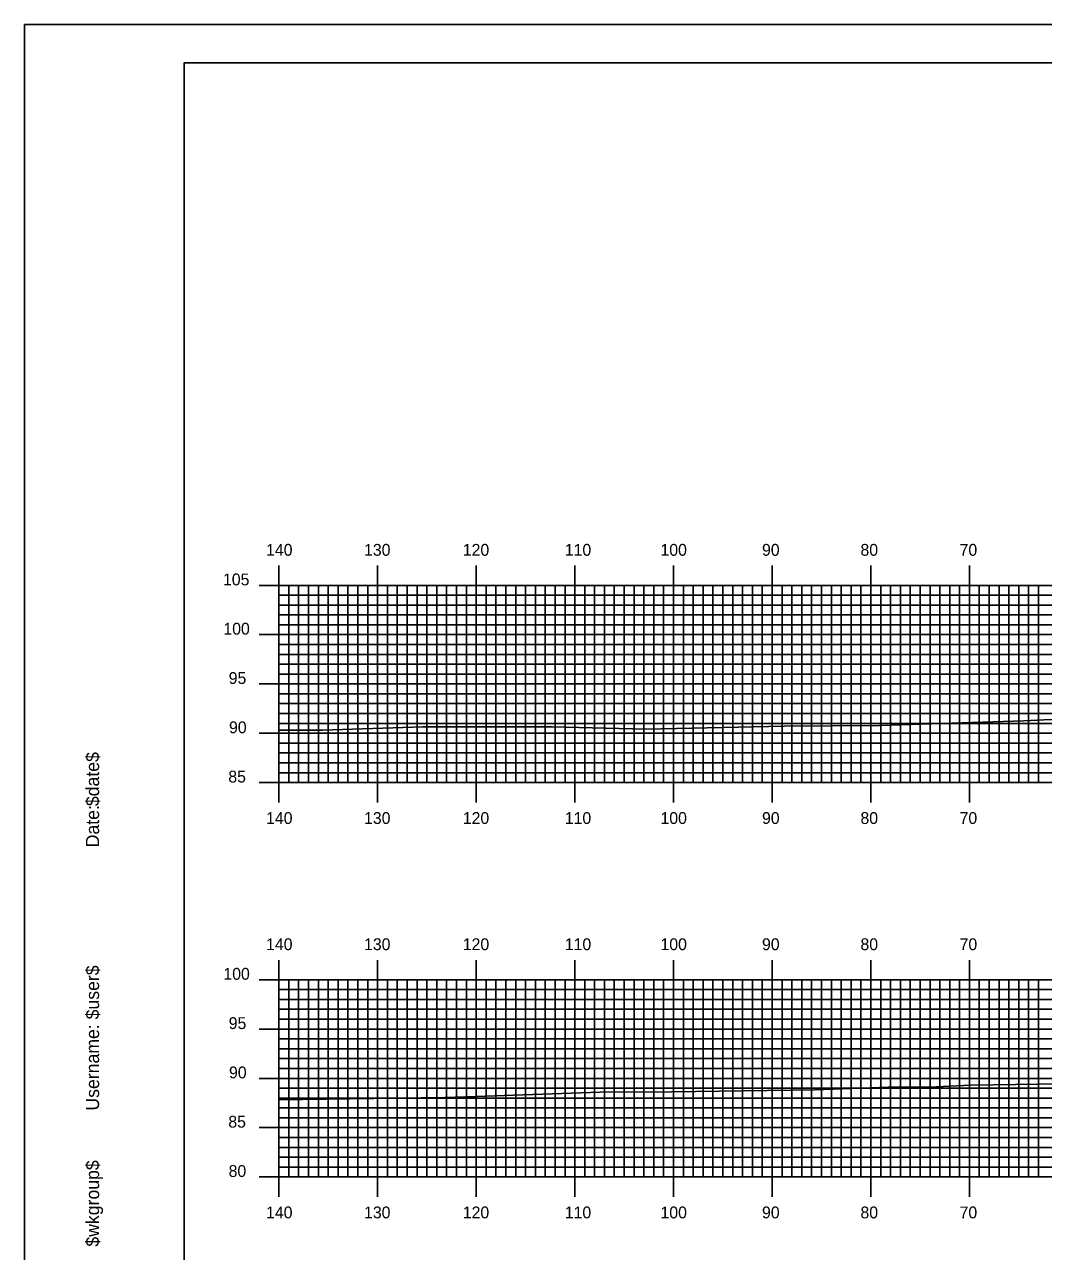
# Model space of a CAD drawing. Extents: x 1777925 to 1778268, y 442591 to 442811.
# Drawn here: x 1777925 to 1778028.3, y 442686.1 to 442810.5 of the extents above; entities that cross this region are included whole.
import ezdxf

# ---------------------------------------------------------------- set-up
doc = ezdxf.new("R2010")
doc.units = 0
for name, color, linetype in [('BORDER', 7, 'Continuous'), ('H_V ANNOTATION', 7, 'Continuous'), ('MAJOR', 7, 'Continuous'), ('MINOR', 7, 'Continuous'), ('PLOT BOUNDARY', 7, 'Continuous'), ('S_Roadway_Centerline', 7, 'Continuous')]:
    doc.layers.add(name, color=color, linetype=linetype)

msp = doc.modelspace()

# ---------------------------------------------------------------- linework, layer by layer
at = {"layer": 'BORDER'}
msp.add_lwpolyline([(1777941.19, 442596.67), (1778261.19, 442596.67), (1778261.19, 442806.67), (1777941.19, 442806.67)], close=True, dxfattribs=at)
at = {"layer": 'MAJOR'}
for p, q in [((1777950.79, 442755.67), (1777950.79, 442753.67)), ((1777960.79, 442755.67), (1777960.79, 442753.67)), ((1777970.79, 442755.67), (1777970.79, 442753.67)), ((1777980.79, 442755.67), (1777980.79, 442753.67)), ((1777990.79, 442755.67), (1777990.79, 442753.67)), ((1778000.79, 442755.67), (1778000.79, 442753.67)), ((1778010.79, 442755.67), (1778010.79, 442753.67)), ((1778020.79, 442755.67), (1778020.79, 442753.67)), ((1777948.79, 442753.67), (1777950.79, 442753.67)), ((1777950.79, 442753.67), (1778230.79, 442753.67)), ((1777950.79, 442733.67), (1777950.79, 442753.67)), ((1777950.79, 442733.67), (1777950.79, 442753.67)), ((1777950.79, 442753.67), (1778230.79, 442753.67)), ((1777960.79, 442733.67), (1777960.79, 442753.67)), ((1777970.79, 442733.67), (1777970.79, 442753.67)), ((1777980.79, 442733.67), (1777980.79, 442753.67)), ((1777990.79, 442733.67), (1777990.79, 442753.67)), ((1778000.79, 442733.67), (1778000.79, 442753.67)), ((1778010.79, 442733.67), (1778010.79, 442753.67)), ((1778020.79, 442733.67), (1778020.79, 442753.67)), ((1777948.79, 442748.67), (1777950.79, 442748.67)), ((1777950.79, 442748.67), (1778230.79, 442748.67)), ((1777948.79, 442743.67), (1777950.79, 442743.67)), ((1777950.79, 442743.67), (1778230.79, 442743.67)), ((1777948.79, 442738.67), (1777950.79, 442738.67)), ((1777950.79, 442738.67), (1778230.79, 442738.67)), ((1777948.79, 442733.67), (1777950.79, 442733.67)), ((1777950.79, 442733.67), (1778230.79, 442733.67)), ((1777950.79, 442733.67), (1778230.79, 442733.67)), ((1777950.79, 442731.66), (1777950.79, 442733.67)), ((1777960.79, 442731.66), (1777960.79, 442733.67)), ((1777970.79, 442731.66), (1777970.79, 442733.67)), ((1777980.79, 442731.66), (1777980.79, 442733.67)), ((1777990.79, 442731.66), (1777990.79, 442733.67)), ((1778000.79, 442731.66), (1778000.79, 442733.67)), ((1778010.79, 442731.66), (1778010.79, 442733.67)), ((1778020.79, 442731.66), (1778020.79, 442733.67)), ((1777950.79, 442715.67), (1777950.79, 442713.67)), ((1777960.79, 442715.67), (1777960.79, 442713.67)), ((1777970.79, 442715.67), (1777970.79, 442713.67)), ((1777980.79, 442715.67), (1777980.79, 442713.67)), ((1777990.79, 442715.67), (1777990.79, 442713.67)), ((1778000.79, 442715.67), (1778000.79, 442713.67)), ((1778010.79, 442715.67), (1778010.79, 442713.67)), ((1778020.79, 442715.67), (1778020.79, 442713.67)), ((1777948.79, 442713.67), (1777950.79, 442713.67)), ((1777950.79, 442713.67), (1778230.79, 442713.67)), ((1777950.79, 442693.67), (1777950.79, 442713.67)), ((1777950.79, 442693.67), (1777950.79, 442713.67)), ((1777950.79, 442713.67), (1778230.79, 442713.67)), ((1777960.79, 442693.67), (1777960.79, 442713.67)), ((1777970.79, 442693.67), (1777970.79, 442713.67)), ((1777980.79, 442693.67), (1777980.79, 442713.67)), ((1777990.79, 442693.67), (1777990.79, 442713.67)), ((1778000.79, 442693.67), (1778000.79, 442713.67)), ((1778010.79, 442693.67), (1778010.79, 442713.67)), ((1778020.79, 442693.67), (1778020.79, 442713.67)), ((1777948.79, 442708.67), (1777950.79, 442708.67)), ((1777950.79, 442708.67), (1778230.79, 442708.67)), ((1777948.79, 442703.67), (1777950.79, 442703.67)), ((1777950.79, 442703.67), (1778230.79, 442703.67)), ((1777948.79, 442698.67), (1777950.79, 442698.67)), ((1777950.79, 442698.67), (1778230.79, 442698.67)), ((1777948.79, 442693.67), (1777950.79, 442693.67)), ((1777950.79, 442693.67), (1778230.79, 442693.67)), ((1777950.79, 442693.67), (1778230.79, 442693.67)), ((1777950.79, 442691.66), (1777950.79, 442693.67)), ((1777960.79, 442691.66), (1777960.79, 442693.67)), ((1777970.79, 442691.66), (1777970.79, 442693.67)), ((1777980.79, 442691.66), (1777980.79, 442693.67)), ((1777990.79, 442691.66), (1777990.79, 442693.67)), ((1778000.79, 442691.66), (1778000.79, 442693.67)), ((1778010.79, 442691.66), (1778010.79, 442693.67)), ((1778020.79, 442691.66), (1778020.79, 442693.67))]:
    msp.add_line(p, q, dxfattribs=at)
at = {"layer": 'MINOR'}
for p, q in [((1777950.79, 442752.67), (1778230.79, 442752.67)), ((1777950.79, 442752.67), (1777952.79, 442752.67)), ((1777951.79, 442733.67), (1777951.79, 442753.67)), ((1777952.79, 442733.67), (1777952.79, 442753.67)), ((1777953.79, 442733.67), (1777953.79, 442753.67)), ((1777954.79, 442733.67), (1777954.79, 442753.67)), ((1777955.79, 442733.67), (1777955.79, 442753.67)), ((1777956.79, 442733.67), (1777956.79, 442753.67)), ((1777957.79, 442733.67), (1777957.79, 442753.67)), ((1777958.79, 442733.67), (1777958.79, 442753.67)), ((1777959.79, 442733.67), (1777959.79, 442753.67)), ((1777961.79, 442733.67), (1777961.79, 442753.67)), ((1777962.79, 442733.67), (1777962.79, 442753.67)), ((1777963.79, 442733.67), (1777963.79, 442753.67)), ((1777964.79, 442733.67), (1777964.79, 442753.67)), ((1777965.79, 442733.67), (1777965.79, 442753.67)), ((1777966.79, 442733.67), (1777966.79, 442753.67)), ((1777967.79, 442733.67), (1777967.79, 442753.67)), ((1777968.79, 442733.67), (1777968.79, 442753.67)), ((1777969.79, 442733.67), (1777969.79, 442753.67)), ((1777971.79, 442733.67), (1777971.79, 442753.67)), ((1777972.79, 442733.67), (1777972.79, 442753.67)), ((1777973.79, 442733.67), (1777973.79, 442753.67)), ((1777974.79, 442733.67), (1777974.79, 442753.67)), ((1777975.79, 442733.67), (1777975.79, 442753.67)), ((1777976.79, 442733.67), (1777976.79, 442753.67)), ((1777977.79, 442733.67), (1777977.79, 442753.67)), ((1777978.79, 442733.67), (1777978.79, 442753.67)), ((1777979.79, 442733.67), (1777979.79, 442753.67)), ((1777981.79, 442733.67), (1777981.79, 442753.67)), ((1777982.79, 442733.67), (1777982.79, 442753.67)), ((1777983.79, 442733.67), (1777983.79, 442753.67)), ((1777984.79, 442733.67), (1777984.79, 442753.67)), ((1777985.79, 442733.67), (1777985.79, 442753.67)), ((1777986.79, 442733.67), (1777986.79, 442753.67)), ((1777987.79, 442733.67), (1777987.79, 442753.67)), ((1777988.79, 442733.67), (1777988.79, 442753.67)), ((1777989.79, 442733.67), (1777989.79, 442753.67)), ((1777991.79, 442733.67), (1777991.79, 442753.67)), ((1777992.79, 442733.67), (1777992.79, 442753.67)), ((1777993.79, 442733.67), (1777993.79, 442753.67)), ((1777994.79, 442733.67), (1777994.79, 442753.67)), ((1777995.79, 442733.67), (1777995.79, 442753.67)), ((1777996.79, 442733.67), (1777996.79, 442753.67)), ((1777997.79, 442733.67), (1777997.79, 442753.67)), ((1777998.79, 442733.67), (1777998.79, 442753.67)), ((1777999.79, 442733.67), (1777999.79, 442753.67)), ((1778001.79, 442733.67), (1778001.79, 442753.67)), ((1778002.79, 442733.67), (1778002.79, 442753.67)), ((1778003.79, 442733.67), (1778003.79, 442753.67)), ((1778004.79, 442733.67), (1778004.79, 442753.67)), ((1778005.79, 442733.67), (1778005.79, 442753.67)), ((1778006.79, 442733.67), (1778006.79, 442753.67)), ((1778007.79, 442733.67), (1778007.79, 442753.67)), ((1778008.79, 442733.67), (1778008.79, 442753.67)), ((1778009.79, 442733.67), (1778009.79, 442753.67)), ((1778011.79, 442733.67), (1778011.79, 442753.67)), ((1778012.79, 442733.67), (1778012.79, 442753.67)), ((1778013.79, 442733.67), (1778013.79, 442753.67)), ((1778014.79, 442733.67), (1778014.79, 442753.67)), ((1778015.79, 442733.67), (1778015.79, 442753.67)), ((1778016.79, 442733.67), (1778016.79, 442753.67)), ((1778017.79, 442733.67), (1778017.79, 442753.67)), ((1778018.79, 442733.67), (1778018.79, 442753.67)), ((1778019.79, 442733.67), (1778019.79, 442753.67)), ((1778021.79, 442733.67), (1778021.79, 442753.67)), ((1778022.79, 442733.67), (1778022.79, 442753.67)), ((1778023.79, 442733.67), (1778023.79, 442753.67)), ((1778024.79, 442733.67), (1778024.79, 442753.67)), ((1778025.79, 442733.67), (1778025.79, 442753.67)), ((1778026.79, 442733.67), (1778026.79, 442753.67)), ((1778027.79, 442733.67), (1778027.79, 442753.67)), ((1777950.79, 442751.67), (1778230.79, 442751.67)), ((1777950.79, 442751.67), (1777952.79, 442751.67)), ((1777950.79, 442750.67), (1778230.79, 442750.67)), ((1777950.79, 442750.67), (1777952.79, 442750.67)), ((1777950.79, 442749.67), (1778230.79, 442749.67)), ((1777950.79, 442749.67), (1777952.79, 442749.67)), ((1777950.79, 442747.67), (1778230.79, 442747.67)), ((1777950.79, 442747.67), (1777952.79, 442747.67)), ((1777950.79, 442746.67), (1778230.79, 442746.67)), ((1777950.79, 442746.67), (1777952.79, 442746.67)), ((1777950.79, 442745.67), (1778230.79, 442745.67)), ((1777950.79, 442745.67), (1777952.79, 442745.67)), ((1777950.79, 442744.67), (1778230.79, 442744.67)), ((1777950.79, 442744.67), (1777952.79, 442744.67)), ((1777950.79, 442742.67), (1778230.79, 442742.67)), ((1777950.79, 442742.67), (1777952.79, 442742.67)), ((1777950.79, 442741.67), (1778230.79, 442741.67)), ((1777950.79, 442741.67), (1777952.79, 442741.67)), ((1777950.79, 442740.67), (1778230.79, 442740.67)), ((1777950.79, 442740.67), (1777952.79, 442740.67)), ((1777950.79, 442739.67), (1778230.79, 442739.67)), ((1777950.79, 442739.67), (1777952.79, 442739.67)), ((1777950.79, 442737.67), (1778230.79, 442737.67)), ((1777950.79, 442737.67), (1777952.79, 442737.67)), ((1777950.79, 442736.67), (1778230.79, 442736.67)), ((1777950.79, 442736.67), (1777952.79, 442736.67)), ((1777950.79, 442735.67), (1778230.79, 442735.67)), ((1777950.79, 442735.67), (1777952.79, 442735.67)), ((1777950.79, 442734.67), (1778230.79, 442734.67)), ((1777950.79, 442734.67), (1777952.79, 442734.67)), ((1777951.79, 442693.67), (1777951.79, 442713.67)), ((1777952.79, 442693.67), (1777952.79, 442713.67)), ((1777953.79, 442693.67), (1777953.79, 442713.67)), ((1777954.79, 442693.67), (1777954.79, 442713.67)), ((1777955.79, 442693.67), (1777955.79, 442713.67)), ((1777956.79, 442693.67), (1777956.79, 442713.67)), ((1777957.79, 442693.67), (1777957.79, 442713.67)), ((1777958.79, 442693.67), (1777958.79, 442713.67)), ((1777959.79, 442693.67), (1777959.79, 442713.67)), ((1777961.79, 442693.67), (1777961.79, 442713.67)), ((1777962.79, 442693.67), (1777962.79, 442713.67)), ((1777963.79, 442693.67), (1777963.79, 442713.67)), ((1777964.79, 442693.67), (1777964.79, 442713.67)), ((1777965.79, 442693.67), (1777965.79, 442713.67)), ((1777966.79, 442693.67), (1777966.79, 442713.67)), ((1777967.79, 442693.67), (1777967.79, 442713.67)), ((1777968.79, 442693.67), (1777968.79, 442713.67)), ((1777969.79, 442693.67), (1777969.79, 442713.67)), ((1777971.79, 442693.67), (1777971.79, 442713.67)), ((1777972.79, 442693.67), (1777972.79, 442713.67)), ((1777973.79, 442693.67), (1777973.79, 442713.67)), ((1777974.79, 442693.67), (1777974.79, 442713.67)), ((1777975.79, 442693.67), (1777975.79, 442713.67)), ((1777976.79, 442693.67), (1777976.79, 442713.67)), ((1777977.79, 442693.67), (1777977.79, 442713.67)), ((1777978.79, 442693.67), (1777978.79, 442713.67)), ((1777979.79, 442693.67), (1777979.79, 442713.67)), ((1777981.79, 442693.67), (1777981.79, 442713.67)), ((1777982.79, 442693.67), (1777982.79, 442713.67)), ((1777983.79, 442693.67), (1777983.79, 442713.67)), ((1777984.79, 442693.67), (1777984.79, 442713.67)), ((1777985.79, 442693.67), (1777985.79, 442713.67)), ((1777986.79, 442693.67), (1777986.79, 442713.67)), ((1777987.79, 442693.67), (1777987.79, 442713.67)), ((1777988.79, 442693.67), (1777988.79, 442713.67)), ((1777989.79, 442693.67), (1777989.79, 442713.67)), ((1777991.79, 442693.67), (1777991.79, 442713.67)), ((1777992.79, 442693.67), (1777992.79, 442713.67)), ((1777993.79, 442693.67), (1777993.79, 442713.67)), ((1777994.79, 442693.67), (1777994.79, 442713.67)), ((1777995.79, 442693.67), (1777995.79, 442713.67)), ((1777996.79, 442693.67), (1777996.79, 442713.67)), ((1777997.79, 442693.67), (1777997.79, 442713.67)), ((1777998.79, 442693.67), (1777998.79, 442713.67)), ((1777999.79, 442693.67), (1777999.79, 442713.67)), ((1778001.79, 442693.67), (1778001.79, 442713.67)), ((1778002.79, 442693.67), (1778002.79, 442713.67)), ((1778003.79, 442693.67), (1778003.79, 442713.67)), ((1778004.79, 442693.67), (1778004.79, 442713.67)), ((1778005.79, 442693.67), (1778005.79, 442713.67)), ((1778006.79, 442693.67), (1778006.79, 442713.67)), ((1778007.79, 442693.67), (1778007.79, 442713.67)), ((1778008.79, 442693.67), (1778008.79, 442713.67)), ((1778009.79, 442693.67), (1778009.79, 442713.67)), ((1778011.79, 442693.67), (1778011.79, 442713.67)), ((1778012.79, 442693.67), (1778012.79, 442713.67)), ((1778013.79, 442693.67), (1778013.79, 442713.67)), ((1778014.79, 442693.67), (1778014.79, 442713.67)), ((1778015.79, 442693.67), (1778015.79, 442713.67)), ((1778016.79, 442693.67), (1778016.79, 442713.67)), ((1778017.79, 442693.67), (1778017.79, 442713.67)), ((1778018.79, 442693.67), (1778018.79, 442713.67)), ((1778019.79, 442693.67), (1778019.79, 442713.67)), ((1778021.79, 442693.67), (1778021.79, 442713.67)), ((1778022.79, 442693.67), (1778022.79, 442713.67)), ((1778023.79, 442693.67), (1778023.79, 442713.67)), ((1778024.79, 442693.67), (1778024.79, 442713.67)), ((1778025.79, 442693.67), (1778025.79, 442713.67)), ((1778026.79, 442693.67), (1778026.79, 442713.67)), ((1778027.79, 442693.67), (1778027.79, 442713.67)), ((1777950.79, 442712.67), (1778230.79, 442712.67)), ((1777950.79, 442712.67), (1777952.79, 442712.67)), ((1777950.79, 442711.67), (1778230.79, 442711.67)), ((1777950.79, 442711.67), (1777952.79, 442711.67)), ((1777950.79, 442710.67), (1778230.79, 442710.67)), ((1777950.79, 442710.67), (1777952.79, 442710.67)), ((1777950.79, 442709.67), (1778230.79, 442709.67)), ((1777950.79, 442709.67), (1777952.79, 442709.67)), ((1777950.79, 442707.67), (1778230.79, 442707.67)), ((1777950.79, 442707.67), (1777952.79, 442707.67)), ((1777950.79, 442706.67), (1778230.79, 442706.67)), ((1777950.79, 442706.67), (1777952.79, 442706.67)), ((1777950.79, 442705.67), (1778230.79, 442705.67)), ((1777950.79, 442705.67), (1777952.79, 442705.67)), ((1777950.79, 442704.67), (1778230.79, 442704.67)), ((1777950.79, 442704.67), (1777952.79, 442704.67)), ((1777950.79, 442702.67), (1778230.79, 442702.67)), ((1777950.79, 442702.67), (1777952.79, 442702.67)), ((1777950.79, 442701.67), (1778230.79, 442701.67)), ((1777950.79, 442701.67), (1777952.79, 442701.67)), ((1777950.79, 442700.67), (1778230.79, 442700.67)), ((1777950.79, 442700.67), (1777952.79, 442700.67)), ((1777950.79, 442699.67), (1778230.79, 442699.67)), ((1777950.79, 442699.67), (1777952.79, 442699.67)), ((1777950.79, 442697.67), (1778230.79, 442697.67)), ((1777950.79, 442697.67), (1777952.79, 442697.67)), ((1777950.79, 442696.67), (1778230.79, 442696.67)), ((1777950.79, 442696.67), (1777952.79, 442696.67)), ((1777950.79, 442695.67), (1778230.79, 442695.67)), ((1777950.79, 442695.67), (1777952.79, 442695.67)), ((1777950.79, 442694.67), (1778230.79, 442694.67)), ((1777950.79, 442694.67), (1777952.79, 442694.67))]:
    msp.add_line(p, q, dxfattribs=at)
at = {"layer": 'PLOT BOUNDARY'}
msp.add_lwpolyline([(1777925, 442590.55), (1778265, 442590.55), (1778265, 442810.55), (1777925, 442810.55)], close=True, dxfattribs=at)
at = {"layer": 'S_Roadway_Centerline'}
for points in [[(1777950.79, 442738.97), (1777955.19, 442738.99), (1777965.37, 442739.31), (1777978.5, 442739.31), (1777988, 442739.1), (1778001.99, 442739.39), (1778011.67, 442739.44), (1778026.29, 442739.93), (1778029.02, 442740.08), (1778032.1, 442740.03), (1778041.42, 442739.94), (1778050.53, 442740.47), (1778053.02, 442740.65), (1778055.18, 442740.61), (1778072.93, 442740.38), (1778079.5, 442740.32), (1778087.5, 442740.31), (1778097.44, 442740.26), (1778101.25, 442740.25), (1778110.99, 442740.24), (1778123.36, 442740.3), (1778145.53, 442740.27)], [(1777950.79, 442701.48), (1777967.62, 442701.73), (1777970.76, 442701.82), (1777974.58, 442701.96), (1777983.34, 442702.28), (1777990.6, 442702.31), (1778005.11, 442702.52), (1778012.55, 442702.76), (1778016.7, 442702.76), (1778020.92, 442702.98), (1778036.73, 442703.21)]]:
    msp.add_lwpolyline(points, dxfattribs=at)

# ---------------------------------------------------------------- texts
at = {"layer": 'BORDER'}
for s, p in [('$date$', (1777932.56, 442731.28)), ('Date:', (1777932.56, 442727.1)), ('$user$', (1777932.56, 442709.65)), ('Username:', (1777932.56, 442700.4)), ('$wkgroup$', (1777932.56, 442686.6))]:
    msp.add_text(s, height=1.339, rotation=90, dxfattribs=at).set_placement(p)
at = {"layer": 'H_V ANNOTATION'}
for s, p in [('140', (1777949.49, 442756.67)), ('130', (1777959.42, 442756.67)), ('120', (1777969.43, 442756.67)), ('110', (1777979.77, 442756.67)), ('100', (1777989.47, 442756.67)), ('90', (1777999.76, 442756.67)), ('80', (1778009.74, 442756.67)), ('70', (1778019.79, 442756.67)), ('105', (1777945.12, 442753.67)), ('100', (1777945.16, 442748.67)), ('95', (1777945.7, 442743.67)), ('90', (1777945.73, 442738.67)), ('85', (1777945.66, 442733.67)), ('140', (1777949.49, 442729.47)), ('130', (1777959.42, 442729.47)), ('120', (1777969.43, 442729.47)), ('110', (1777979.77, 442729.47)), ('100', (1777989.47, 442729.47)), ('90', (1777999.76, 442729.47)), ('80', (1778009.74, 442729.47)), ('70', (1778019.79, 442729.47)), ('140', (1777949.49, 442716.67)), ('130', (1777959.42, 442716.67)), ('120', (1777969.43, 442716.67)), ('110', (1777979.77, 442716.67)), ('100', (1777989.47, 442716.67)), ('90', (1777999.76, 442716.67)), ('80', (1778009.74, 442716.67)), ('70', (1778019.79, 442716.67)), ('100', (1777945.16, 442713.67)), ('95', (1777945.7, 442708.67)), ('90', (1777945.73, 442703.67)), ('85', (1777945.66, 442698.67)), ('80', (1777945.69, 442693.67)), ('140', (1777949.49, 442689.47)), ('130', (1777959.42, 442689.47)), ('120', (1777969.43, 442689.47)), ('110', (1777979.77, 442689.47)), ('100', (1777989.47, 442689.47)), ('90', (1777999.76, 442689.47)), ('80', (1778009.74, 442689.47)), ('70', (1778019.79, 442689.47))]:
    msp.add_text(s, height=1.2, dxfattribs=at).set_placement(p)
at = {"layer": 'MAJOR'}
for p in [(1777950.78, 442733.67), (1777950.78, 442693.67)]:
    msp.add_text('-', height=0.012, dxfattribs=at).set_placement(p)

doc.saveas('drawing.dxf')
